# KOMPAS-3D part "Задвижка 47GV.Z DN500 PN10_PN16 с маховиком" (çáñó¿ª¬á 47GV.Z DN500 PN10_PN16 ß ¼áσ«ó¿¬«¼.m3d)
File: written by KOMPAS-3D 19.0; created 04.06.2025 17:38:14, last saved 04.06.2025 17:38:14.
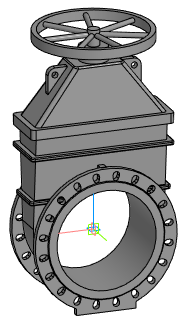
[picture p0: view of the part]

Document properties: Автор: Евгений; Полное имя файла: E:\Dendor Работа Сачек\3D для проекитирвщиков\2.1 Тип 47GV, 47GV.Z Задвижка клиновая фланцевая с обрезиненным клином\stp_Тип 47GV.Z. Задвижка DN40-DN350 с маховиком\Задвижка 47GV.Z DN500 PN10_PN16 с маховиком.m3d

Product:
- Part/product: Задвижка 47GV.Z DN500 PN10_PN16 с маховиком

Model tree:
1. Операция без истории:1  (labels: Задвижка 47GV.Z DN500 PN10_PN16 с маховиком)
